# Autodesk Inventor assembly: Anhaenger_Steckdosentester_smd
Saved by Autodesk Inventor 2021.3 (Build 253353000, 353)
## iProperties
Created: 2023-03
Part Number: Anhaenger_Steckdosentester_smd
Document SubType Name: Assembly
Designer: AdminForWorker
Title: Anhaenger_Steckdosentester_smd v5
Author: AdminForWorker
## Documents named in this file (13)
- z:\worker\convert-fusion-r08-cosv3\tmp\job-1\3553\output\files\82b4d9ad-b575-4129-b9ca-4964d6b72adf\fc125e9c-f42f-44bd-9d18-de6d32f6b85c.iam
- z:\worker\convert-fusion-r08-cosv3\tmp\job-1\3553\output\files\82b4d9ad-b575-4129-b9ca-4964d6b72adf\Platine_1 v1.iam
- z:\worker\convert-fusion-r08-cosv3\tmp\job-1\3553\output\files\82b4d9ad-b575-4129-b9ca-4964d6b72adf\Platine_2_smd v2.iam
- z:\worker\convert-fusion-r08-cosv3\tmp\job-1\3553\output\files\82b4d9ad-b575-4129-b9ca-4964d6b72adf\960050042 (rev1) v2.iam
- z:\worker\convert-fusion-r08-cosv3\tmp\job-1\3553\output\files\82b4d9ad-b575-4129-b9ca-4964d6b72adf\960050042 (rev1) v2_1.iam
- z:\worker\convert-fusion-r08-cosv3\tmp\job-1\3553\output\files\82b4d9ad-b575-4129-b9ca-4964d6b72adf\960050042 (rev1) v2_2.iam
- z:\worker\convert-fusion-r08-cosv3\tmp\job-1\3553\output\files\82b4d9ad-b575-4129-b9ca-4964d6b72adf\960050042 (rev1) v2_3.iam
- z:\worker\convert-fusion-r08-cosv3\tmp\job-1\3553\output\files\82b4d9ad-b575-4129-b9ca-4964d6b72adf\960050042 (rev1) v2_4.iam
- z:\worker\convert-fusion-r08-cosv3\tmp\job-1\3553\output\files\82b4d9ad-b575-4129-b9ca-4964d6b72adf\960050042 (rev1) v2_5.iam
- z:\worker\convert-fusion-r08-cosv3\tmp\job-1\3553\output\files\82b4d9ad-b575-4129-b9ca-4964d6b72adf\960050042 (rev1) v2_6.iam
- z:\worker\convert-fusion-r08-cosv3\tmp\job-1\3553\output\files\82b4d9ad-b575-4129-b9ca-4964d6b72adf\WUERTH 039403 hexagon nut DIN 6923  M3 8 A2K.ipt
- z:\worker\convert-fusion-r08-cosv3\tmp\job-1\3553\output\files\82b4d9ad-b575-4129-b9ca-4964d6b72adf\WUERTH 421313 12 screw DIN 34805-2 SHR-DIN34805_2-010.9-TX10-(A2K)-M3X12 010.9 Verzinkt.ipt
- z:\worker\convert-fusion-r08-cosv3\tmp\job-1\3553\output\files\82b4d9ad-b575-4129-b9ca-4964d6b72adf\WUERTH 422025 8 raised head screw 2.5x8 10.9 Verzinkt.ipt
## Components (25 placed, 6 different names)
1. Platine_1 v1:1 [sub-assembly]
2. Platine_2_smd v2:1 [sub-assembly]
3. 960050042 (rev1) v2:1 [sub-assembly]
4. 960050042 (rev1) v2:2 [sub-assembly]
5. 960050042 (rev1) v2:3 [sub-assembly]
6. 960050042 (rev1) v2:4 [sub-assembly]
7. 960050042 (rev1) v2:5 [sub-assembly]
8. 960050042 (rev1) v2:6 [sub-assembly]
9. 960050042 (rev1) v2:7 [sub-assembly]
10. WUERTH 039403 hexagon nut DIN 6923  M3 8 A2K:1
11. WUERTH 039403 hexagon nut DIN 6923  M3 8 A2K:2
12. WUERTH 039403 hexagon nut DIN 6923  M3 8 A2K:3
13. WUERTH 039403 hexagon nut DIN 6923  M3 8 A2K:4
14. WUERTH 039403 hexagon nut DIN 6923  M3 8 A2K:5
15. WUERTH 039403 hexagon nut DIN 6923  M3 8 A2K:6
16. WUERTH 039403 hexagon nut DIN 6923  M3 8 A2K:7
17. WUERTH 421313 12 screw DIN 34805-2 SHR-DIN34805/2-010.9-TX10-(A2K)-M3X12 010.9 Verzinkt:1
18. WUERTH 421313 12 screw DIN 34805-2 SHR-DIN34805/2-010.9-TX10-(A2K)-M3X12 010.9 Verzinkt:2
19. WUERTH 421313 12 screw DIN 34805-2 SHR-DIN34805/2-010.9-TX10-(A2K)-M3X12 010.9 Verzinkt:3
20. WUERTH 421313 12 screw DIN 34805-2 SHR-DIN34805/2-010.9-TX10-(A2K)-M3X12 010.9 Verzinkt:4
21. WUERTH 421313 12 screw DIN 34805-2 SHR-DIN34805/2-010.9-TX10-(A2K)-M3X12 010.9 Verzinkt:5
22. WUERTH 421313 12 screw DIN 34805-2 SHR-DIN34805/2-010.9-TX10-(A2K)-M3X12 010.9 Verzinkt:6
23. WUERTH 421313 12 screw DIN 34805-2 SHR-DIN34805/2-010.9-TX10-(A2K)-M3X12 010.9 Verzinkt:7
24. WUERTH 422025 8 raised head screw 2.5x8 10.9 Verzinkt:1
25. WUERTH 422025 8 raised head screw 2.5x8 10.9 Verzinkt:2
